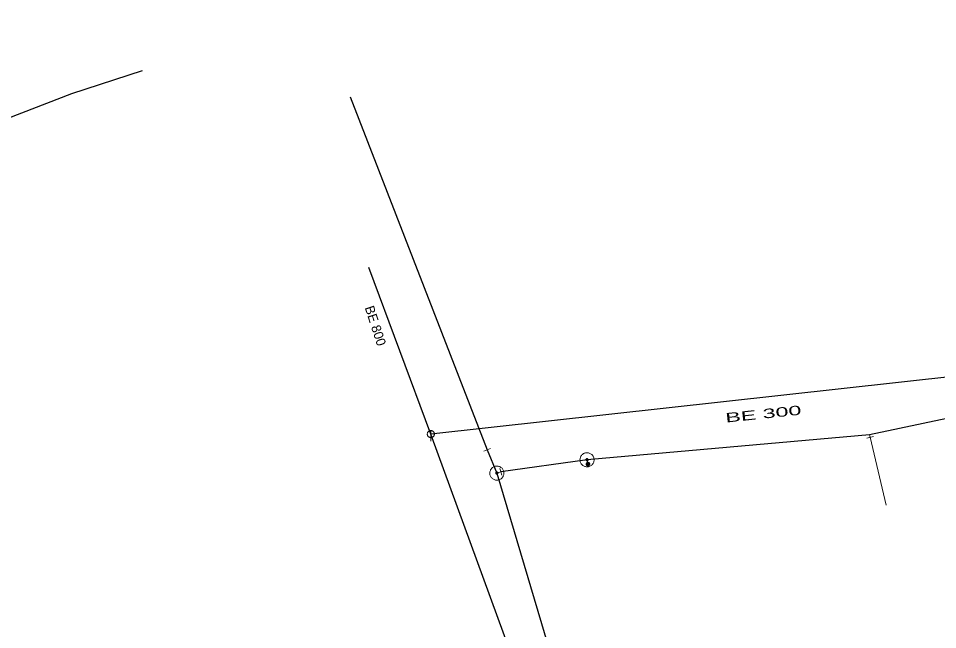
# Model space of a CAD drawing. Extents: x -687515 to -686506, y -974029 to -973461.
# Drawn here: x -687166.1 to -687100.9, y -973504.8 to -973461.4 of the extents above; entities that cross this region are included whole.
import ezdxf
from ezdxf.enums import TextEntityAlignment as Align

# ---------------------------------------------------------------- set-up
doc = ezdxf.new("R2010")
doc.units = 0
doc.header["$LTSCALE"] = 0.27
for name, color, linetype, lineweight in [('1', 7, 'Continuous', 13), ('13', 7, 'Continuous', 13), ('14', 7, 'Continuous', 25), ('17', 7, 'Continuous', 25), ('22', 7, 'Continuous', 13), ('34', 7, 'Continuous', 13), ('47', 7, 'Continuous', 13), ('9', 7, 'Continuous', 13)]:
    doc.layers.add(name, color=color, linetype=linetype, lineweight=lineweight)

msp = doc.modelspace()

# ---------------------------------------------------------------- linework, layer by layer
at = {"layer": '13'}
msp.add_line((-687105.68, -973491.149), (-687104.553, -973495.955), dxfattribs=at)
at = {"layer": '14'}
for p, q in [((-687136.829, -973490.92), (-687141.227, -973479.113)), ((-687089.909, -973485.751), (-687136.83, -973490.92))]:
    msp.add_line(p, q, dxfattribs=at)
at = {"layer": '14', "lineweight": 13}
for p, q in [((-687105.732, -973490.966), (-687105.68, -973491.149)), ((-687125.756, -973492.743), (-687125.69, -973493.05)), ((-687131.869, -973493.599), (-687132.15, -973493.689))]:
    msp.add_line(p, q, dxfattribs=at)
at = {"layer": '14'}
msp.add_lwpolyline([(-687110.498, -973563.624), (-687122.706, -973529.611), (-687136.829, -973490.92)], dxfattribs=at)
at = {"layer": '17'}
msp.add_line((-687125.756, -973492.743), (-687131.869, -973493.599), dxfattribs=at)
for points in [[(-686909.161, -973466.235), (-686913.807, -973461.442), (-687024.592, -973492.592), (-687041.911, -973493.995), (-687051.861, -973493.177), (-687062.728, -973488.354), (-687072.464, -973486.138), (-687076.669, -973485.884), (-687084.129, -973486.42), (-687105.732, -973490.966), (-687125.756, -973492.743)], [(-687157.299, -973465.166), (-687162.314, -973466.789), (-687172.973, -973470.914), (-687222.892, -973489.136), (-687223.779, -973490.391)], [(-687142.549, -973467.009), (-687132.839, -973492.042), (-687132.15, -973493.689)], [(-687132.15, -973493.689), (-687128.537, -973505.866), (-687118.206, -973534.968)]]:
    msp.add_lwpolyline(points, dxfattribs=at)
at = {"layer": '22'}
msp.add_line((-687136.829, -973490.668), (-687136.83, -973491.412), dxfattribs=at)
msp.add_lwpolyline([(-687136.578, -973490.92), (-687136.579, -973490.894), (-687136.583, -973490.868), (-687136.589, -973490.842), (-687136.599, -973490.818), (-687136.611, -973490.794), (-687136.625, -973490.772), (-687136.642, -973490.751), (-687136.66, -973490.733), (-687136.681, -973490.716), (-687136.703, -973490.702), (-687136.727, -973490.69), (-687136.751, -973490.68), (-687136.777, -973490.674), (-687136.803, -973490.67), (-687136.829, -973490.668), (-687136.855, -973490.669), (-687136.881, -973490.673), (-687136.907, -973490.679), (-687136.932, -973490.689), (-687136.955, -973490.701), (-687136.977, -973490.715), (-687136.998, -973490.732), (-687137.016, -973490.75), (-687137.033, -973490.771), (-687137.047, -973490.793), (-687137.059, -973490.817), (-687137.069, -973490.841), (-687137.076, -973490.867), (-687137.08, -973490.893), (-687137.081, -973490.919), (-687137.081, -973490.945), (-687137.077, -973490.971), (-687137.07, -973490.997), (-687137.06, -973491.022), (-687137.048, -973491.045), (-687137.034, -973491.067), (-687137.017, -973491.088), (-687136.999, -973491.106), (-687136.978, -973491.123), (-687136.956, -973491.137), (-687136.933, -973491.149), (-687136.908, -973491.159), (-687136.882, -973491.166), (-687136.856, -973491.17), (-687136.83, -973491.172), (-687136.804, -973491.171), (-687136.778, -973491.167), (-687136.752, -973491.16), (-687136.728, -973491.15), (-687136.704, -973491.138), (-687136.682, -973491.124), (-687136.661, -973491.107), (-687136.643, -973491.089), (-687136.626, -973491.068), (-687136.612, -973491.046), (-687136.6, -973491.023), (-687136.59, -973490.998), (-687136.584, -973490.972), (-687136.58, -973490.946)], close=True, dxfattribs=at)
at = {"layer": '34'}
for p, q in [((-687105.921, -973491.205), (-687105.438, -973491.092)), ((-687133.067, -973492.137), (-687132.61, -973491.946)), ((-687131.795, -973493.835), (-687131.942, -973493.362))]:
    msp.add_line(p, q, dxfattribs=at)
at = {"layer": '47'}
for points in [[(-687125.278, -973492.594), (-687125.296, -973492.545), (-687125.319, -973492.498), (-687125.348, -973492.454), (-687125.379, -973492.413), (-687125.416, -973492.375), (-687125.457, -973492.342), (-687125.5, -973492.313), (-687125.547, -973492.289), (-687125.595, -973492.269), (-687125.645, -973492.255), (-687125.697, -973492.246), (-687125.749, -973492.243), (-687125.801, -973492.245), (-687125.853, -973492.252), (-687125.904, -973492.265), (-687125.953, -973492.283), (-687126, -973492.306), (-687126.045, -973492.335), (-687126.085, -973492.366), (-687126.123, -973492.403), (-687126.156, -973492.444), (-687126.186, -973492.488), (-687126.21, -973492.534), (-687126.23, -973492.582), (-687126.243, -973492.632), (-687126.252, -973492.684), (-687126.256, -973492.737), (-687126.253, -973492.788), (-687126.246, -973492.84), (-687126.233, -973492.891), (-687126.215, -973492.94), (-687126.192, -973492.987), (-687126.164, -973493.032), (-687126.132, -973493.072), (-687126.095, -973493.11), (-687126.055, -973493.143), (-687126.011, -973493.173), (-687125.965, -973493.197), (-687125.916, -973493.217), (-687125.866, -973493.23), (-687125.814, -973493.239), (-687125.762, -973493.243), (-687125.71, -973493.24), (-687125.658, -973493.233), (-687125.607, -973493.22), (-687125.558, -973493.202), (-687125.511, -973493.179), (-687125.467, -973493.151), (-687125.426, -973493.119), (-687125.388, -973493.082), (-687125.355, -973493.042), (-687125.326, -973492.999), (-687125.302, -973492.952), (-687125.282, -973492.903), (-687125.268, -973492.853), (-687125.259, -973492.801), (-687125.256, -973492.75), (-687125.258, -973492.697), (-687125.265, -973492.645)], [(-687125.677, -973492.718), (-687125.68, -973492.71), (-687125.684, -973492.703), (-687125.688, -973492.695), (-687125.694, -973492.689), (-687125.7, -973492.682), (-687125.707, -973492.677), (-687125.714, -973492.672), (-687125.721, -973492.668), (-687125.729, -973492.665), (-687125.737, -973492.663), (-687125.746, -973492.661), (-687125.755, -973492.661), (-687125.763, -973492.661), (-687125.771, -973492.662), (-687125.78, -973492.664), (-687125.788, -973492.667), (-687125.795, -973492.671), (-687125.803, -973492.675), (-687125.809, -973492.681), (-687125.816, -973492.687), (-687125.821, -973492.694), (-687125.826, -973492.701), (-687125.83, -973492.708), (-687125.834, -973492.717), (-687125.835, -973492.724), (-687125.837, -973492.733), (-687125.837, -973492.742), (-687125.837, -973492.75), (-687125.836, -973492.758), (-687125.834, -973492.767), (-687125.831, -973492.775), (-687125.827, -973492.782), (-687125.823, -973492.79), (-687125.817, -973492.796), (-687125.811, -973492.803), (-687125.805, -973492.808), (-687125.797, -973492.813), (-687125.79, -973492.817), (-687125.781, -973492.821), (-687125.774, -973492.822), (-687125.765, -973492.824), (-687125.756, -973492.824), (-687125.748, -973492.824), (-687125.74, -973492.823), (-687125.731, -973492.821), (-687125.723, -973492.818), (-687125.716, -973492.814), (-687125.708, -973492.81), (-687125.702, -973492.804), (-687125.695, -973492.798), (-687125.69, -973492.792), (-687125.685, -973492.784), (-687125.681, -973492.777), (-687125.678, -973492.769), (-687125.676, -973492.761), (-687125.674, -973492.752), (-687125.674, -973492.743), (-687125.674, -973492.735), (-687125.675, -973492.727)], [(-687131.986, -973494.161), (-687131.938, -973494.141), (-687131.892, -973494.117), (-687131.849, -973494.087), (-687131.808, -973494.054), (-687131.772, -973494.016), (-687131.74, -973493.974), (-687131.713, -973493.93), (-687131.69, -973493.883), (-687131.672, -973493.835), (-687131.659, -973493.784), (-687131.651, -973493.731), (-687131.65, -973493.679), (-687131.653, -973493.627), (-687131.663, -973493.575), (-687131.677, -973493.525), (-687131.697, -973493.477), (-687131.721, -973493.431), (-687131.751, -973493.387), (-687131.784, -973493.347), (-687131.822, -973493.311), (-687131.864, -973493.279), (-687131.908, -973493.251), (-687131.955, -973493.228), (-687132.004, -973493.21), (-687132.054, -973493.198), (-687132.107, -973493.19), (-687132.159, -973493.188), (-687132.211, -973493.192), (-687132.263, -973493.202), (-687132.313, -973493.216), (-687132.361, -973493.236), (-687132.407, -973493.26), (-687132.451, -973493.289), (-687132.491, -973493.323), (-687132.527, -973493.361), (-687132.56, -973493.402), (-687132.588, -973493.446), (-687132.61, -973493.493), (-687132.628, -973493.543), (-687132.64, -973493.593), (-687132.648, -973493.646), (-687132.65, -973493.697), (-687132.646, -973493.75), (-687132.636, -973493.802), (-687132.622, -973493.852), (-687132.602, -973493.9), (-687132.578, -973493.946), (-687132.549, -973493.989), (-687132.515, -973494.03), (-687132.477, -973494.066), (-687132.436, -973494.099), (-687132.392, -973494.126), (-687132.345, -973494.149), (-687132.296, -973494.166), (-687132.245, -973494.179), (-687132.192, -973494.187), (-687132.141, -973494.188), (-687132.088, -973494.185), (-687132.036, -973494.175)], [(-687132.123, -973493.766), (-687132.114, -973493.763), (-687132.107, -973493.759), (-687132.1, -973493.754), (-687132.094, -973493.749), (-687132.088, -973493.742), (-687132.083, -973493.735), (-687132.078, -973493.728), (-687132.074, -973493.721), (-687132.071, -973493.712), (-687132.069, -973493.704), (-687132.068, -973493.695), (-687132.068, -973493.687), (-687132.068, -973493.678), (-687132.069, -973493.67), (-687132.072, -973493.662), (-687132.075, -973493.653), (-687132.079, -973493.646), (-687132.084, -973493.639), (-687132.089, -973493.633), (-687132.096, -973493.627), (-687132.103, -973493.622), (-687132.11, -973493.617), (-687132.117, -973493.613), (-687132.126, -973493.61), (-687132.134, -973493.608), (-687132.143, -973493.607), (-687132.151, -973493.607), (-687132.16, -973493.607), (-687132.168, -973493.608), (-687132.176, -973493.611), (-687132.185, -973493.614), (-687132.192, -973493.618), (-687132.199, -973493.623), (-687132.205, -973493.628), (-687132.211, -973493.635), (-687132.217, -973493.641), (-687132.221, -973493.649), (-687132.225, -973493.656), (-687132.228, -973493.665), (-687132.23, -973493.673), (-687132.231, -973493.682), (-687132.231, -973493.69), (-687132.231, -973493.699), (-687132.23, -973493.707), (-687132.227, -973493.715), (-687132.224, -973493.724), (-687132.22, -973493.731), (-687132.215, -973493.738), (-687132.21, -973493.744), (-687132.203, -973493.75), (-687132.197, -973493.756), (-687132.189, -973493.76), (-687132.182, -973493.764), (-687132.173, -973493.767), (-687132.165, -973493.769), (-687132.156, -973493.77), (-687132.148, -973493.77), (-687132.139, -973493.77), (-687132.131, -973493.769)]]:
    msp.add_lwpolyline(points, close=True, dxfattribs=at)
at = {"layer": '9'}
for points in [[(-687125.563, -973493.05), (-687125.565, -973493.037), (-687125.566, -973493.024), (-687125.57, -973493.011), (-687125.575, -973492.999), (-687125.58, -973492.987), (-687125.588, -973492.976), (-687125.595, -973492.966), (-687125.605, -973492.956), (-687125.615, -973492.948), (-687125.627, -973492.941), (-687125.639, -973492.935), (-687125.651, -973492.93), (-687125.664, -973492.927), (-687125.676, -973492.925), (-687125.69, -973492.924), (-687125.703, -973492.925), (-687125.715, -973492.927), (-687125.728, -973492.93), (-687125.74, -973492.935), (-687125.752, -973492.941), (-687125.764, -973492.948), (-687125.774, -973492.956), (-687125.784, -973492.966), (-687125.791, -973492.976), (-687125.799, -973492.987), (-687125.804, -973492.999), (-687125.809, -973493.011), (-687125.813, -973493.024), (-687125.815, -973493.037), (-687125.816, -973493.05), (-687125.815, -973493.063), (-687125.813, -973493.076), (-687125.809, -973493.089), (-687125.804, -973493.101), (-687125.799, -973493.113), (-687125.791, -973493.124), (-687125.784, -973493.134), (-687125.774, -973493.144), (-687125.764, -973493.152), (-687125.752, -973493.159), (-687125.74, -973493.165), (-687125.728, -973493.17), (-687125.715, -973493.173), (-687125.703, -973493.175), (-687125.69, -973493.176), (-687125.676, -973493.175), (-687125.664, -973493.173), (-687125.651, -973493.17), (-687125.639, -973493.165), (-687125.627, -973493.159), (-687125.615, -973493.152), (-687125.605, -973493.144), (-687125.595, -973493.134), (-687125.588, -973493.124), (-687125.58, -973493.113), (-687125.575, -973493.101), (-687125.57, -973493.089), (-687125.566, -973493.076), (-687125.565, -973493.063)], [(-687125.583, -973493.05), (-687125.583, -973493.039), (-687125.585, -973493.028), (-687125.588, -973493.017), (-687125.593, -973493.007), (-687125.598, -973492.997), (-687125.603, -973492.988), (-687125.61, -973492.979), (-687125.619, -973492.971), (-687125.627, -973492.964), (-687125.637, -973492.958), (-687125.647, -973492.953), (-687125.656, -973492.949), (-687125.668, -973492.946), (-687125.678, -973492.944), (-687125.69, -973492.944), (-687125.701, -973492.944), (-687125.712, -973492.946), (-687125.723, -973492.949), (-687125.732, -973492.953), (-687125.742, -973492.958), (-687125.752, -973492.964), (-687125.761, -973492.971), (-687125.769, -973492.979), (-687125.776, -973492.988), (-687125.781, -973492.997), (-687125.786, -973493.007), (-687125.791, -973493.017), (-687125.794, -973493.028), (-687125.796, -973493.039), (-687125.796, -973493.05), (-687125.796, -973493.061), (-687125.794, -973493.072), (-687125.791, -973493.083), (-687125.786, -973493.093), (-687125.781, -973493.103), (-687125.776, -973493.112), (-687125.769, -973493.121), (-687125.761, -973493.129), (-687125.752, -973493.136), (-687125.742, -973493.142), (-687125.732, -973493.147), (-687125.723, -973493.151), (-687125.712, -973493.154), (-687125.701, -973493.156), (-687125.69, -973493.156), (-687125.678, -973493.156), (-687125.668, -973493.154), (-687125.656, -973493.151), (-687125.647, -973493.147), (-687125.637, -973493.142), (-687125.627, -973493.136), (-687125.619, -973493.129), (-687125.61, -973493.121), (-687125.603, -973493.112), (-687125.598, -973493.103), (-687125.593, -973493.093), (-687125.588, -973493.083), (-687125.585, -973493.072), (-687125.583, -973493.061)], [(-687125.602, -973493.05), (-687125.603, -973493.041), (-687125.605, -973493.032), (-687125.607, -973493.023), (-687125.61, -973493.015), (-687125.615, -973493.007), (-687125.62, -973492.999), (-687125.625, -973492.992), (-687125.632, -973492.986), (-687125.639, -973492.98), (-687125.647, -973492.975), (-687125.654, -973492.971), (-687125.663, -973492.968), (-687125.671, -973492.965), (-687125.681, -973492.964), (-687125.69, -973492.963), (-687125.698, -973492.964), (-687125.708, -973492.965), (-687125.717, -973492.968), (-687125.725, -973492.971), (-687125.732, -973492.975), (-687125.74, -973492.98), (-687125.747, -973492.986), (-687125.754, -973492.992), (-687125.759, -973492.999), (-687125.764, -973493.007), (-687125.769, -973493.015), (-687125.772, -973493.023), (-687125.774, -973493.032), (-687125.776, -973493.041), (-687125.777, -973493.05), (-687125.776, -973493.059), (-687125.774, -973493.068), (-687125.772, -973493.077), (-687125.769, -973493.085), (-687125.764, -973493.093), (-687125.759, -973493.101), (-687125.754, -973493.108), (-687125.747, -973493.114), (-687125.74, -973493.12), (-687125.732, -973493.125), (-687125.725, -973493.129), (-687125.717, -973493.132), (-687125.708, -973493.135), (-687125.698, -973493.136), (-687125.69, -973493.137), (-687125.681, -973493.136), (-687125.671, -973493.135), (-687125.663, -973493.132), (-687125.654, -973493.129), (-687125.647, -973493.125), (-687125.639, -973493.12), (-687125.632, -973493.114), (-687125.625, -973493.108), (-687125.62, -973493.101), (-687125.615, -973493.093), (-687125.61, -973493.085), (-687125.607, -973493.077), (-687125.605, -973493.068), (-687125.603, -973493.059)], [(-687125.622, -973493.05), (-687125.622, -973493.043), (-687125.625, -973493.036), (-687125.625, -973493.029), (-687125.629, -973493.023), (-687125.632, -973493.017), (-687125.636, -973493.011), (-687125.639, -973493.005), (-687125.644, -973493), (-687125.651, -973492.996), (-687125.656, -973492.992), (-687125.663, -973492.989), (-687125.669, -973492.986), (-687125.676, -973492.985), (-687125.683, -973492.983), (-687125.69, -973492.983), (-687125.696, -973492.983), (-687125.703, -973492.985), (-687125.71, -973492.986), (-687125.717, -973492.989), (-687125.723, -973492.992), (-687125.728, -973492.996), (-687125.735, -973493), (-687125.74, -973493.005), (-687125.744, -973493.011), (-687125.747, -973493.017), (-687125.75, -973493.023), (-687125.754, -973493.029), (-687125.755, -973493.036), (-687125.757, -973493.043), (-687125.757, -973493.05), (-687125.757, -973493.057), (-687125.755, -973493.064), (-687125.754, -973493.071), (-687125.75, -973493.077), (-687125.747, -973493.084), (-687125.744, -973493.089), (-687125.74, -973493.095), (-687125.735, -973493.1), (-687125.728, -973493.104), (-687125.723, -973493.108), (-687125.717, -973493.111), (-687125.71, -973493.114), (-687125.703, -973493.116), (-687125.696, -973493.117), (-687125.69, -973493.117), (-687125.683, -973493.117), (-687125.676, -973493.116), (-687125.669, -973493.114), (-687125.663, -973493.111), (-687125.656, -973493.108), (-687125.651, -973493.104), (-687125.644, -973493.1), (-687125.639, -973493.095), (-687125.636, -973493.089), (-687125.632, -973493.084), (-687125.629, -973493.077), (-687125.625, -973493.071), (-687125.625, -973493.064), (-687125.622, -973493.057)], [(-687125.642, -973493.05), (-687125.642, -973493.045), (-687125.644, -973493.04), (-687125.644, -973493.035), (-687125.647, -973493.031), (-687125.649, -973493.026), (-687125.652, -973493.022), (-687125.654, -973493.019), (-687125.659, -973493.015), (-687125.661, -973493.012), (-687125.666, -973493.009), (-687125.671, -973493.007), (-687125.674, -973493.005), (-687125.679, -973493.004), (-687125.684, -973493.003), (-687125.69, -973493.003), (-687125.695, -973493.003), (-687125.7, -973493.004), (-687125.705, -973493.005), (-687125.708, -973493.007), (-687125.713, -973493.009), (-687125.718, -973493.012), (-687125.722, -973493.015), (-687125.725, -973493.019), (-687125.727, -973493.022), (-687125.73, -973493.026), (-687125.732, -973493.031), (-687125.735, -973493.035), (-687125.735, -973493.04), (-687125.737, -973493.045), (-687125.737, -973493.05), (-687125.737, -973493.055), (-687125.735, -973493.06), (-687125.735, -973493.065), (-687125.732, -973493.069), (-687125.73, -973493.074), (-687125.727, -973493.078), (-687125.725, -973493.082), (-687125.722, -973493.085), (-687125.718, -973493.088), (-687125.713, -973493.091), (-687125.708, -973493.093), (-687125.705, -973493.095), (-687125.7, -973493.096), (-687125.695, -973493.097), (-687125.69, -973493.097), (-687125.684, -973493.097), (-687125.679, -973493.096), (-687125.674, -973493.095), (-687125.671, -973493.093), (-687125.666, -973493.091), (-687125.661, -973493.088), (-687125.659, -973493.085), (-687125.654, -973493.082), (-687125.652, -973493.078), (-687125.649, -973493.074), (-687125.647, -973493.069), (-687125.644, -973493.065), (-687125.644, -973493.06), (-687125.642, -973493.055)], [(-687125.663, -973493.05), (-687125.663, -973493.047), (-687125.663, -973493.044), (-687125.664, -973493.042), (-687125.664, -973493.039), (-687125.666, -973493.036), (-687125.668, -973493.034), (-687125.669, -973493.032), (-687125.671, -973493.03), (-687125.674, -973493.028), (-687125.676, -973493.026), (-687125.678, -973493.025), (-687125.681, -973493.024), (-687125.683, -973493.023), (-687125.686, -973493.023), (-687125.69, -973493.023), (-687125.693, -973493.023), (-687125.696, -973493.023), (-687125.698, -973493.024), (-687125.701, -973493.025), (-687125.703, -973493.026), (-687125.705, -973493.028), (-687125.708, -973493.03), (-687125.71, -973493.032), (-687125.712, -973493.034), (-687125.713, -973493.036), (-687125.715, -973493.039), (-687125.715, -973493.042), (-687125.717, -973493.044), (-687125.717, -973493.047), (-687125.718, -973493.05), (-687125.717, -973493.053), (-687125.717, -973493.056), (-687125.715, -973493.059), (-687125.715, -973493.061), (-687125.713, -973493.064), (-687125.712, -973493.066), (-687125.71, -973493.069), (-687125.708, -973493.071), (-687125.705, -973493.072), (-687125.703, -973493.074), (-687125.701, -973493.075), (-687125.698, -973493.076), (-687125.696, -973493.077), (-687125.693, -973493.077), (-687125.69, -973493.078), (-687125.686, -973493.077), (-687125.683, -973493.077), (-687125.681, -973493.076), (-687125.678, -973493.075), (-687125.676, -973493.074), (-687125.674, -973493.072), (-687125.671, -973493.071), (-687125.669, -973493.069), (-687125.668, -973493.066), (-687125.666, -973493.064), (-687125.664, -973493.061), (-687125.664, -973493.059), (-687125.663, -973493.056), (-687125.663, -973493.053)], [(-687125.681, -973493.05), (-687125.681, -973493.049), (-687125.681, -973493.048), (-687125.683, -973493.048), (-687125.683, -973493.047), (-687125.683, -973493.046), (-687125.683, -973493.045), (-687125.683, -973493.045), (-687125.684, -973493.044), (-687125.684, -973493.044), (-687125.686, -973493.043), (-687125.686, -973493.043), (-687125.688, -973493.043), (-687125.688, -973493.042), (-687125.688, -973493.042), (-687125.69, -973493.042), (-687125.691, -973493.042), (-687125.691, -973493.042), (-687125.691, -973493.043), (-687125.693, -973493.043), (-687125.693, -973493.043), (-687125.695, -973493.044), (-687125.695, -973493.044), (-687125.696, -973493.045), (-687125.696, -973493.045), (-687125.696, -973493.046), (-687125.696, -973493.047), (-687125.698, -973493.048), (-687125.698, -973493.048), (-687125.698, -973493.049), (-687125.698, -973493.05), (-687125.698, -973493.051), (-687125.698, -973493.052), (-687125.698, -973493.052), (-687125.696, -973493.053), (-687125.696, -973493.054), (-687125.696, -973493.055), (-687125.696, -973493.055), (-687125.695, -973493.056), (-687125.695, -973493.056), (-687125.693, -973493.057), (-687125.693, -973493.057), (-687125.691, -973493.058), (-687125.691, -973493.058), (-687125.691, -973493.058), (-687125.69, -973493.058), (-687125.688, -973493.058), (-687125.688, -973493.058), (-687125.688, -973493.058), (-687125.686, -973493.057), (-687125.686, -973493.057), (-687125.684, -973493.056), (-687125.684, -973493.056), (-687125.683, -973493.055), (-687125.683, -973493.055), (-687125.683, -973493.054), (-687125.683, -973493.053), (-687125.683, -973493.052), (-687125.681, -973493.052), (-687125.681, -973493.051)]]:
    msp.add_lwpolyline(points, close=True, dxfattribs=at)

# ---------------------------------------------------------------- texts
at = {"layer": '1'}
msp.add_text('BE 800', height=0.6667, rotation=288, dxfattribs=at).set_placement((-687141.07, -973483.343), align=Align.CENTER)
at = {"layer": '1', "width": 1.85}
msp.add_text('BE 300', height=0.6667, rotation=6, dxfattribs=at).set_placement((-687113.224, -973489.823), align=Align.CENTER)

doc.saveas('drawing.dxf')
